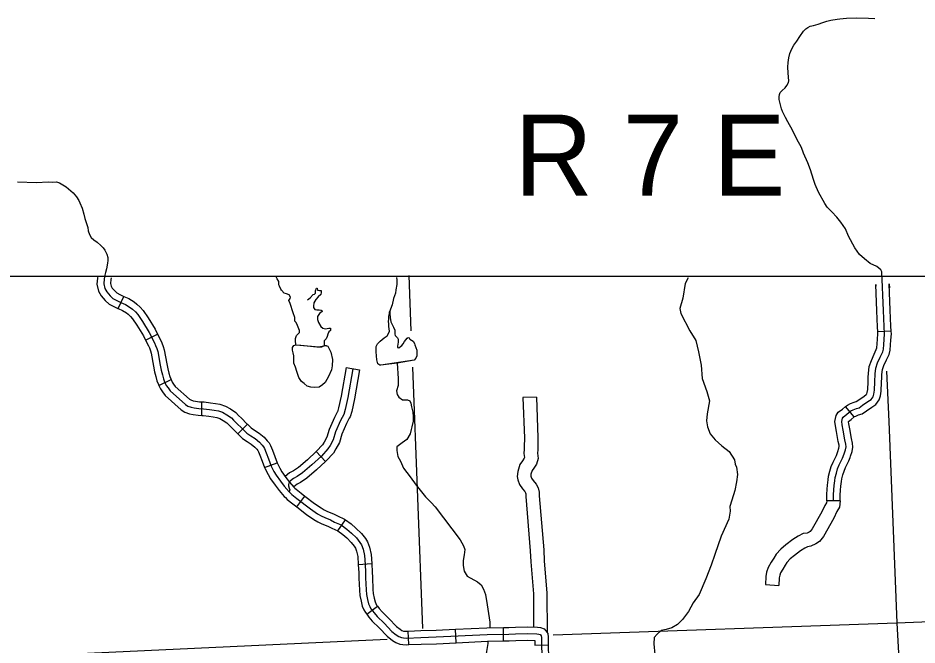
# Model space of a CAD drawing. Extents: x -5566 to 1759129, y -3726 to 731467.
# Drawn here: x -4614.7 to -4538.9, y 480.8 to 533.8 of the extents above; entities that cross this region are included whole.
import ezdxf

# ---------------------------------------------------------------- set-up
doc = ezdxf.new("R2010")
doc.units = 0
doc.layers.add('Default', color=7, linetype='Continuous')
doc.layers.add('R_No Plot', color=7, linetype='Continuous')

msp = doc.modelspace()

# ---------------------------------------------------------------- linework, layer by layer
at = {"layer": 'Default'}
for p, q in [((-4606.271, 509.255), (-4605.779, 510.282)), ((-4603.95, 506.571), (-4602.937, 507.092)), ((-4541.044, 507.331), (-4542.181, 507.275)), ((-4587.028, 504.264), (-4585.905, 504.072)), ((-4602.833, 502.765), (-4601.804, 503.252)), ((-4599.22, 500.231), (-4599.193, 501.37)), ((-4544.166, 500.106), (-4544.898, 500.978)), ((-4596.157, 498.672), (-4595.36, 499.486)), ((-4589.547, 497.175), (-4588.768, 496.344)), ((-4593.908, 495.823), (-4592.838, 496.213)), ((-4591.201, 492.503), (-4590.512, 493.41)), ((-4545.339, 493.025), (-4546.478, 493.025)), ((-4587.743, 490.482), (-4587.079, 491.408)), ((-4586.006, 487.651), (-4584.869, 487.728)), ((-4585.294, 483.437), (-4584.387, 484.126)), ((-4581.745, 480.873), (-4581.796, 482.011)), ((-4577.737, 481.033), (-4577.791, 482.171)), ((-4573.746, 481.186), (-4573.769, 482.325)), ((-4571.117, 480.842), (-4569.978, 480.866))]:
    msp.add_line(p, q, dxfattribs=at)
for points in [[(-4542.192, 504.659), (-4541.971, 505.159), (-4541.766, 505.585), (-4541.699, 505.828), (-4541.663, 506.225), (-4541.633, 506.629), (-4541.604, 507.129), (-4541.633, 507.731), (-4541.692, 509.083), (-4541.824, 512.355), (-4541.927, 512.531), (-4542.265, 512.811), (-4542.809, 513.046), (-4543.294, 513.443), (-4543.734, 513.825), (-4544.116, 514.383), (-4544.645, 515.368), (-4544.91, 515.971), (-4545.306, 516.559), (-4545.644, 516.955), (-4546.056, 517.411), (-4546.438, 517.823), (-4546.658, 518.131), (-4547.172, 519.065), (-4547.474, 519.719), (-4547.606, 520.137), (-4547.863, 520.975), (-4548.091, 521.548), (-4548.436, 522.374), (-4548.627, 522.845), (-4549.002, 523.55), (-4549.362, 524.3), (-4549.766, 525.005), (-4549.964, 525.373), (-4550.221, 525.887), (-4550.294, 526.115), (-4550.449, 526.666), (-4550.5, 526.901), (-4550.508, 527.122), (-4550.463, 527.328), (-4550.403, 527.481), (-4550.236, 527.666), (-4550.001, 527.893), (-4549.839, 528.077), (-4549.721, 528.349), (-4549.677, 528.467), (-4549.699, 528.783), (-4549.736, 529.15), (-4549.766, 529.642), (-4549.736, 530.017), (-4549.685, 530.414), (-4549.589, 530.782), (-4549.442, 531.171), (-4549.251, 531.487), (-4549.016, 531.818), (-4548.752, 532.229), (-4548.451, 532.685), (-4548.252, 532.883), (-4548.091, 532.986), (-4547.892, 533.082), (-4547.613, 533.148), (-4547.194, 533.273), (-4546.812, 533.412), (-4546.467, 533.523), (-4546.129, 533.589), (-4545.6, 533.692), (-4545.383, 533.721), (-4544.825, 533.765), (-4543.965, 533.787), (-4542.973, 533.773), (-4542.434, 533.745)], [(-4614.752, 519.942), (-4613.155, 519.893), (-4612.184, 519.942), (-4611.803, 519.936), (-4611.472, 519.946), (-4611.201, 519.874), (-4610.661, 519.518), (-4610.071, 519.026), (-4609.77, 518.688), (-4609.591, 518.381), (-4609.495, 518.175), (-4609.315, 517.717), (-4609.174, 517.213), (-4609.08, 516.852), (-4608.972, 516.506), (-4608.83, 516.088), (-4608.785, 515.825), (-4608.685, 515.516), (-4608.553, 515.24), (-4608.326, 515.043), (-4608.043, 514.853), (-4607.73, 514.589), (-4607.535, 514.384), (-4607.38, 514.177), (-4607.232, 513.857), (-4607.146, 513.55), (-4607.134, 513.31), (-4607.159, 513.083), (-4607.238, 512.604), (-4607.331, 512.297), (-4607.397, 512.078), (-4607.446, 511.761), (-4607.481, 511.341), (-4607.392, 510.933), (-4607.234, 510.651), (-4606.952, 510.337), (-4606.703, 510.11), (-4606.369, 509.943), (-4606.032, 509.772), (-4605.64, 509.584), (-4605.248, 509.351), (-4605.052, 509.201), (-4604.807, 508.971), (-4604.601, 508.746), (-4604.215, 508.163), (-4603.644, 507.221), (-4603.198, 506.354), (-4603.103, 506.146), (-4603.006, 505.876), (-4602.926, 505.632), (-4602.721, 504.481), (-4602.633, 504.044), (-4602.537, 503.644), (-4602.453, 503.32), (-4602.349, 503.073), (-4602.205, 502.768), (-4602.057, 502.546), (-4601.87, 502.296), (-4600.589, 501.157), (-4600.389, 501.023), (-4600.098, 500.923), (-4599.839, 500.865), (-4599.464, 500.807), (-4599.06, 500.797), (-4598.547, 500.74), (-4598.156, 500.673), (-4597.813, 500.616), (-4597.453, 500.499), (-4597.097, 500.29), (-4596.713, 500.03), (-4596.528, 499.832), (-4596.27, 499.581), (-4595.803, 499.123), (-4595.411, 498.739), (-4595.069, 498.514), (-4594.703, 498.272), (-4594.339, 497.975), (-4594.119, 497.731), (-4594.011, 497.59), (-4593.911, 497.422), (-4593.769, 497.08), (-4593.569, 496.555), (-4593.344, 495.938), (-4593.119, 495.506), (-4592.928, 495.172), (-4592.569, 494.664), (-4592.252, 494.247), (-4591.847, 493.785)], [(-4581.535, 507.382), (-4581.718, 512.048)], [(-4607.989, 511.976), (-4608.012, 511.829), (-4608.056, 511.303), (-4607.931, 510.729), (-4607.7, 510.317), (-4607.357, 509.935), (-4607.028, 509.635), (-4606.625, 509.434), (-4606.283, 509.261), (-4606.271, 509.255)], [(-4606.855, 511.857), (-4606.88, 511.694), (-4606.906, 511.378), (-4606.854, 511.138), (-4606.768, 510.985), (-4606.547, 510.739), (-4606.377, 510.584), (-4606.113, 510.452), (-4605.78, 510.283), (-4605.779, 510.282)], [(-4591.264, 506.195), (-4591.312, 506.545), (-4591.312, 506.729), (-4591.212, 506.979), (-4590.962, 507.229), (-4590.979, 507.396), (-4591.146, 507.813), (-4591.246, 508.063), (-4591.346, 508.196), (-4591.346, 508.496), (-4591.512, 508.88), (-4591.762, 509.68), (-4591.879, 509.93), (-4591.762, 510.097), (-4591.729, 510.214), (-4591.829, 510.397), (-4592.062, 510.497), (-4592.262, 510.564), (-4592.479, 510.797), (-4592.529, 510.881), (-4592.662, 511.131), (-4592.696, 511.248), (-4592.696, 511.431), (-4592.712, 511.548), (-4592.846, 511.765), (-4592.946, 511.931), (-4592.962, 511.979)], [(-4582.779, 511.88), (-4582.754, 511.683), (-4582.756, 511.27), (-4582.825, 510.824), (-4582.879, 510.539), (-4583.024, 510.104), (-4583.149, 509.571), (-4583.386, 508.982)], [(-4558.184, 511.838), (-4558.431, 511.381), (-4558.622, 510.118), (-4558.881, 509.243), (-4558.802, 508.826), (-4558.04, 507.384), (-4557.525, 506.559), (-4557.298, 505.611), (-4557.072, 504.458), (-4556.991, 503.336), (-4556.6, 502.238), (-4556.371, 501.449), (-4556.567, 500.35), (-4556.622, 499.783), (-4556.558, 499.267), (-4556.323, 498.68), (-4555.905, 498.156), (-4555.327, 497.657), (-4554.719, 497.172), (-4554.277, 496.489), (-4554.205, 496.111), (-4554.093, 495.857), (-4554.017, 495.25), (-4554.1, 494.62), (-4554.238, 493.895), (-4554.484, 493.077), (-4554.664, 492.537), (-4554.636, 492.136), (-4554.731, 491.473), (-4555.387, 490.02), (-4555.936, 488.484), (-4556.24, 487.584), (-4556.69, 486.424), (-4557.261, 485.105), (-4557.756, 484.404), (-4558.145, 483.682), (-4558.664, 482.984), (-4559.077, 482.582), (-4559.541, 482.299), (-4560.028, 482.16), (-4560.448, 482.062), (-4560.804, 481.761), (-4561.034, 481.483), (-4561.083, 480.938), (-4560.999, 480.034)], [(-4542.181, 507.275), (-4542.202, 507.705), (-4542.261, 509.059), (-4542.351, 511.286)], [(-4542.351, 511.286), (-4542.345, 511.139)], [(-4541.044, 507.331), (-4541.064, 507.757), (-4541.123, 509.107), (-4541.213, 511.332)], [(-4541.213, 511.332), (-4541.199, 510.992)], [(-4590.279, 509.996), (-4590.079, 510.146), (-4589.812, 510.429), (-4589.695, 510.463), (-4589.629, 510.563), (-4589.629, 510.746), (-4589.545, 510.98), (-4589.479, 510.963), (-4589.445, 510.813), (-4589.279, 510.763), (-4589.145, 510.763), (-4589.129, 510.713), (-4589.129, 510.613), (-4589.179, 510.429), (-4589.379, 510.246), (-4589.595, 510.013), (-4589.762, 509.729), (-4589.779, 509.462), (-4589.779, 509.329), (-4589.679, 509.162), (-4589.512, 509.145), (-4589.295, 509.145), (-4589.145, 509.129), (-4589.045, 509.062), (-4589.045, 508.995), (-4589.279, 508.845), (-4589.445, 508.579), (-4589.445, 508.328), (-4589.362, 508.078), (-4589.179, 507.745), (-4588.995, 507.595), (-4588.762, 507.545), (-4588.495, 507.595), (-4588.345, 507.595), (-4588.345, 507.411), (-4588.479, 507.278), (-4588.579, 507.094), (-4588.645, 506.894), (-4588.729, 506.694), (-4588.895, 506.527), (-4588.895, 506.144)], [(-4605.779, 510.282), (-4605.371, 510.087), (-4604.928, 509.823), (-4604.684, 509.636), (-4604.401, 509.372), (-4604.151, 509.097), (-4603.734, 508.468), (-4603.146, 507.499), (-4602.937, 507.092)], [(-4606.271, 509.255), (-4605.909, 509.082), (-4605.568, 508.879), (-4605.421, 508.765), (-4605.212, 508.571), (-4605.052, 508.395), (-4604.696, 507.858), (-4604.141, 506.943), (-4603.95, 506.571)], [(-4583.829, 506.777), (-4583.561, 506.952), (-4583.458, 507.148), (-4583.386, 507.333), (-4583.397, 507.55), (-4583.417, 507.725), (-4583.438, 507.972), (-4583.448, 508.158), (-4583.438, 508.353), (-4583.417, 508.601), (-4583.386, 508.817), (-4583.386, 508.982), (-4583.335, 508.992), (-4583.335, 508.817), (-4583.304, 508.487), (-4583.263, 508.137), (-4583.047, 507.684), (-4582.933, 507.416), (-4582.913, 507.272), (-4582.913, 507.138), (-4582.913, 507.076), (-4582.902, 506.973), (-4582.707, 506.787), (-4582.655, 506.653), (-4582.655, 506.416), (-4582.686, 506.066), (-4582.686, 505.973), (-4582.583, 505.922), (-4582.459, 506.035), (-4582.336, 506.128), (-4582.223, 506.262), (-4582.109, 506.458), (-4581.883, 506.746), (-4581.79, 506.798), (-4581.728, 506.787), (-4581.656, 506.674), (-4581.378, 506.499), (-4581.254, 506.313), (-4581.234, 506.179)], [(-4602.937, 507.092), (-4602.685, 506.602), (-4602.575, 506.36), (-4602.467, 506.061), (-4602.372, 505.772), (-4602.161, 504.586), (-4602.077, 504.166), (-4601.985, 503.783), (-4601.912, 503.503), (-4601.829, 503.306), (-4601.804, 503.252)], [(-4581.234, 506.179), (-4581.069, 505.747), (-4581.069, 505.273), (-4581.151, 505.067), (-4581.296, 504.902), (-4582.717, 504.644), (-4584.118, 504.459), (-4584.2, 504.479), (-4584.355, 504.582), (-4584.447, 504.922), (-4584.509, 505.592), (-4584.509, 505.809), (-4584.488, 506.045), (-4584.385, 506.272), (-4584.149, 506.489), (-4583.829, 506.777)], [(-4542.977, 503.454), (-4542.964, 503.766), (-4542.915, 504.355), (-4542.719, 504.875), (-4542.489, 505.398), (-4542.301, 505.786), (-4542.262, 505.93), (-4542.23, 506.272), (-4542.202, 506.666), (-4542.174, 507.131), (-4542.181, 507.275)], [(-4541.839, 503.408), (-4541.827, 503.695), (-4541.793, 504.102), (-4541.664, 504.444), (-4541.454, 504.92), (-4541.23, 505.385), (-4541.137, 505.726), (-4541.095, 506.178), (-4541.065, 506.591), (-4541.034, 507.126), (-4541.044, 507.331)], [(-4603.95, 506.571), (-4603.711, 506.105), (-4603.631, 505.931), (-4603.545, 505.69), (-4603.48, 505.493), (-4603.281, 504.375), (-4603.19, 503.921), (-4603.09, 503.506), (-4602.994, 503.137), (-4602.87, 502.841), (-4602.833, 502.765)], [(-4591.297, 504.294), (-4591.447, 504.628), (-4591.447, 504.878), (-4591.447, 505.262), (-4591.514, 505.512), (-4591.564, 505.728), (-4591.547, 505.962), (-4591.431, 506.129), (-4591.264, 506.195), (-4590.847, 506.162), (-4589.497, 506.012), (-4589.297, 506.012), (-4589.08, 506.029), (-4588.83, 506.129), (-4588.714, 506.129), (-4588.58, 506.079), (-4588.33, 505.578), (-4588.18, 504.945)], [(-4591.264, 506.195), (-4589.297, 506.012), (-4588.83, 506.129), (-4588.58, 506.079)], [(-4588.18, 504.945), (-4588.197, 504.411), (-4588.264, 504.078), (-4588.514, 503.527), (-4588.797, 503.01), (-4589.014, 502.81), (-4589.314, 502.627), (-4589.68, 502.594), (-4589.997, 502.61), (-4590.33, 502.71), (-4590.58, 502.91), (-4590.797, 503.094), (-4591.014, 503.444), (-4591.181, 503.928), (-4591.297, 504.294)], [(-4581.296, 504.902), (-4584.118, 504.459)], [(-4582.717, 504.644), (-4582.652, 503.338), (-4582.655, 502.748), (-4582.779, 502.316), (-4582.727, 501.986), (-4582.583, 501.782), (-4582.284, 501.535), (-4581.862, 501.543), (-4581.646, 501.473), (-4581.563, 501.257), (-4581.522, 500.948), (-4581.409, 500.494), (-4581.368, 500.134), (-4581.387, 499.732), (-4581.493, 499.273), (-4581.533, 499.031), (-4581.618, 498.687), (-4581.917, 498.198), (-4582.298, 497.912), (-4582.748, 497.59), (-4582.768, 497.27), (-4582.665, 496.765), (-4582.455, 496.362), (-4582.183, 495.788), (-4581.637, 495.037), (-4581.131, 494.345), (-4580.337, 493.362), (-4579.857, 492.882), (-4579.52, 492.51), (-4577.423, 489.719), (-4577.13, 489.227), (-4577.015, 488.904), (-4577.06, 488.459), (-4577.159, 487.978), (-4577.146, 487.559), (-4577.083, 487.081), (-4576.815, 486.669), (-4575.949, 486.182)], [(-4545.909, 493.025), (-4545.909, 493.523), (-4545.881, 493.952), (-4545.853, 494.298), (-4545.812, 494.713), (-4545.77, 494.99), (-4545.673, 495.364), (-4545.563, 495.723), (-4545.425, 496.055), (-4545.148, 496.633), (-4545.01, 496.992), (-4544.899, 497.324), (-4544.857, 497.574), (-4544.871, 497.795), (-4544.954, 498.155), (-4545.106, 498.985), (-4545.189, 499.441), (-4545.217, 499.704), (-4545.189, 499.87), (-4545.162, 499.995), (-4545.093, 500.092), (-4544.788, 500.327), (-4544.443, 500.617), (-4544.249, 500.7), (-4543.986, 500.811), (-4543.751, 500.88), (-4543.461, 501.088), (-4543.004, 501.392), (-4542.741, 501.572), (-4542.575, 501.807), (-4542.506, 502.029), (-4542.451, 502.347), (-4542.423, 503.053), (-4542.396, 503.731), (-4542.354, 504.229), (-4542.192, 504.659)], [(-4586.467, 504.168), (-4586.883, 501.733), (-4587.117, 500.716), (-4587.233, 500.316), (-4587.5, 499.799), (-4587.934, 498.832), (-4588.134, 498.165), (-4588.384, 497.698), (-4588.567, 497.398), (-4589.117, 496.797), (-4589.917, 496.047), (-4590.701, 495.38), (-4591.176, 495.063), (-4591.484, 494.896), (-4591.734, 494.7), (-4591.817, 494.617), (-4591.872, 494.521), (-4591.901, 494.405), (-4591.888, 494.284), (-4591.842, 494.1), (-4591.792, 493.958), (-4591.797, 493.875), (-4591.847, 493.785)], [(-4587.028, 504.264), (-4587.442, 501.845), (-4587.668, 500.859), (-4587.765, 500.528), (-4587.776, 500.506)], [(-4585.905, 504.072), (-4586.325, 501.621), (-4586.565, 500.572), (-4586.702, 500.104), (-4586.764, 499.984)], [(-4580.553, 482.224), (-4581.415, 504.309)], [(-4541.441, 503.971), (-4541.244, 499.717), (-4540.573, 482.722)], [(-4601.804, 503.252), (-4601.708, 503.049), (-4601.592, 502.875), (-4601.448, 502.684), (-4600.24, 501.609), (-4600.135, 501.538), (-4599.942, 501.472), (-4599.733, 501.425), (-4599.413, 501.375), (-4599.193, 501.37)], [(-4544.898, 500.978), (-4544.744, 501.108), (-4544.472, 501.225), (-4544.178, 501.348), (-4544.004, 501.4), (-4543.784, 501.557), (-4543.323, 501.864), (-4543.148, 501.984), (-4543.092, 502.063), (-4543.061, 502.163), (-4543.019, 502.407), (-4542.992, 503.075), (-4542.977, 503.454)], [(-4544.166, 500.106), (-4544.141, 500.127), (-4544.026, 500.176), (-4543.795, 500.274), (-4543.498, 500.361), (-4543.137, 500.619), (-4542.685, 500.92), (-4542.335, 501.16), (-4542.058, 501.552), (-4541.951, 501.894), (-4541.883, 502.287), (-4541.854, 503.03), (-4541.839, 503.408)], [(-4602.833, 502.765), (-4602.702, 502.487), (-4602.522, 502.217), (-4602.291, 501.909), (-4600.938, 500.705), (-4600.644, 500.509), (-4600.253, 500.375), (-4599.946, 500.305), (-4599.515, 500.238), (-4599.22, 500.231)], [(-4599.193, 501.37), (-4599.022, 501.366), (-4598.468, 501.304), (-4598.061, 501.235), (-4597.677, 501.171), (-4597.218, 501.021), (-4596.793, 500.772), (-4596.34, 500.466), (-4596.121, 500.23), (-4595.872, 499.989), (-4595.404, 499.529), (-4595.36, 499.486)], [(-4570.977, 501.773), (-4572.116, 501.733), (-4571.996, 498.307), (-4571.998, 497.603), (-4572.001, 497.389), (-4572.043, 497.012), (-4571.993, 496.689), (-4572.018, 496.616), (-4572.151, 496.404), (-4572.381, 496.073), (-4572.555, 495.498), (-4572.607, 495.072), (-4572.538, 494.787), (-4572.403, 494.392), (-4572.148, 494.043), (-4571.959, 493.808), (-4571.9, 493.696), (-4571.875, 493.603), (-4571.875, 493.388), (-4571.493, 488.806), (-4571.462, 487.869), (-4571.226, 485.157), (-4571.212, 482.37)], [(-4570.977, 501.773), (-4570.857, 498.326), (-4570.859, 497.595), (-4570.863, 497.319), (-4570.894, 497.037), (-4570.824, 496.584), (-4570.984, 496.12), (-4571.201, 495.776), (-4571.342, 495.572), (-4571.436, 495.261), (-4571.451, 495.138), (-4571.444, 495.106), (-4571.381, 494.924), (-4571.245, 494.737), (-4571.002, 494.436), (-4570.834, 494.115), (-4570.736, 493.755), (-4570.736, 493.435), (-4570.355, 488.872), (-4570.325, 487.938), (-4570.087, 485.21), (-4570.071, 481.91)], [(-4545.581, 497.094), (-4545.546, 497.185), (-4545.453, 497.462), (-4545.43, 497.603), (-4545.437, 497.713), (-4545.512, 498.039), (-4545.667, 498.883), (-4545.754, 499.361), (-4545.792, 499.722), (-4545.749, 499.979), (-4545.693, 500.231), (-4545.507, 500.491), (-4545.146, 500.77), (-4544.898, 500.978)], [(-4599.22, 500.231), (-4599.098, 500.228), (-4598.627, 500.176), (-4598.251, 500.112), (-4597.949, 500.061), (-4597.688, 499.976), (-4597.401, 499.808), (-4597.085, 499.595), (-4596.935, 499.433), (-4596.667, 499.174), (-4596.202, 498.716), (-4596.157, 498.672)], [(-4587.776, 500.506), (-4588.014, 500.046), (-4588.468, 499.031), (-4588.663, 498.383), (-4588.878, 497.981), (-4589.024, 497.742), (-4589.522, 497.198), (-4589.547, 497.175)], [(-4586.764, 499.984), (-4586.987, 499.552), (-4587.399, 498.633), (-4587.604, 497.946), (-4587.889, 497.415), (-4588.11, 497.054), (-4588.712, 496.397), (-4588.768, 496.344)], [(-4544.517, 496.686), (-4544.473, 496.8), (-4544.344, 497.187), (-4544.285, 497.544), (-4544.306, 497.877), (-4544.396, 498.27), (-4544.546, 499.087), (-4544.625, 499.522), (-4544.643, 499.687), (-4544.636, 499.724), (-4544.431, 499.883), (-4544.166, 500.106)], [(-4595.36, 499.486), (-4595.052, 499.185), (-4594.756, 498.99), (-4594.365, 498.732), (-4593.944, 498.388), (-4593.681, 498.095), (-4593.539, 497.911), (-4593.401, 497.678), (-4593.24, 497.291), (-4593.036, 496.754), (-4592.838, 496.213)], [(-4596.157, 498.672), (-4595.77, 498.294), (-4595.383, 498.039), (-4595.041, 497.813), (-4594.733, 497.561), (-4594.557, 497.366), (-4594.483, 497.269), (-4594.421, 497.166), (-4594.299, 496.87), (-4594.103, 496.356), (-4593.908, 495.823)], [(-4589.547, 497.175), (-4590.297, 496.472), (-4591.044, 495.835), (-4591.47, 495.552), (-4591.797, 495.374), (-4592.168, 495.084)], [(-4546.478, 493.025), (-4546.478, 493.542), (-4546.449, 493.993), (-4546.421, 494.349), (-4546.377, 494.784), (-4546.329, 495.104), (-4546.222, 495.519), (-4546.099, 495.917), (-4545.945, 496.288), (-4545.671, 496.858), (-4545.581, 497.094)], [(-4592.838, 496.213), (-4592.822, 496.168), (-4592.619, 495.779), (-4592.447, 495.479), (-4592.109, 495), (-4591.811, 494.607), (-4591.431, 494.175), (-4591.348, 494.092), (-4591.245, 493.989), (-4590.838, 493.658), (-4590.512, 493.41)], [(-4588.768, 496.344), (-4589.537, 495.622), (-4590.357, 494.925), (-4590.882, 494.575), (-4591.171, 494.418), (-4591.452, 494.198)], [(-4545.339, 493.025), (-4545.339, 493.505), (-4545.313, 493.911), (-4545.286, 494.247), (-4545.246, 494.643), (-4545.211, 494.876), (-4545.125, 495.208), (-4545.027, 495.53), (-4544.904, 495.823), (-4544.624, 496.407), (-4544.517, 496.686)], [(-4593.908, 495.823), (-4593.867, 495.708), (-4593.619, 495.232), (-4593.408, 494.866), (-4593.029, 494.327), (-4592.694, 493.886), (-4592.263, 493.395), (-4592.154, 493.287), (-4592.009, 493.142), (-4591.542, 492.762), (-4591.201, 492.503)], [(-4591.847, 493.785), (-4591.751, 493.689), (-4591.627, 493.565), (-4591.19, 493.21), (-4590.042, 492.338), (-4589.455, 491.931), (-4589.149, 491.754), (-4588.839, 491.604), (-4588.35, 491.399), (-4588.002, 491.222), (-4587.46, 490.981), (-4586.96, 490.622), (-4586.593, 490.297), (-4586.168, 489.88)], [(-4590.512, 493.41), (-4589.707, 492.799), (-4589.15, 492.413), (-4588.881, 492.257), (-4588.605, 492.123), (-4588.111, 491.917), (-4587.757, 491.737), (-4587.175, 491.477), (-4587.079, 491.408)], [(-4546.478, 493.025), (-4546.512, 492.854), (-4546.636, 492.625), (-4546.897, 492.089), (-4547.711, 490.649), (-4547.893, 490.418), (-4547.961, 490.371), (-4548.143, 490.288), (-4548.463, 490.245), (-4548.884, 490.025), (-4549.343, 489.75), (-4549.934, 489.291), (-4550.357, 488.928), (-4550.744, 488.509), (-4550.953, 488.187), (-4551.165, 487.848), (-4551.438, 487.399), (-4551.569, 486.987), (-4551.621, 486.641), (-4551.664, 485.952), (-4550.527, 485.881)], [(-4545.339, 493.025), (-4545.416, 492.483), (-4545.624, 492.103), (-4545.888, 491.56), (-4546.762, 490.012), (-4547.105, 489.578), (-4547.397, 489.376), (-4547.824, 489.182), (-4548.112, 489.143), (-4548.327, 489.031), (-4548.698, 488.808), (-4549.214, 488.408), (-4549.565, 488.107), (-4549.842, 487.807), (-4549.992, 487.575), (-4550.195, 487.251), (-4550.393, 486.924), (-4550.456, 486.728), (-4550.487, 486.521), (-4550.527, 485.881)], [(-4591.201, 492.503), (-4590.377, 491.877), (-4589.761, 491.45), (-4589.416, 491.25), (-4589.073, 491.084), (-4588.589, 490.882), (-4588.247, 490.708), (-4587.745, 490.484), (-4587.743, 490.482)], [(-4587.079, 491.408), (-4586.604, 491.068), (-4586.205, 490.714), (-4585.742, 490.26), (-4585.408, 489.83), (-4585.232, 489.544), (-4585.055, 489.096), (-4584.919, 488.476), (-4584.869, 487.728)], [(-4587.743, 490.482), (-4587.316, 490.176), (-4586.982, 489.88), (-4586.594, 489.5), (-4586.345, 489.18), (-4586.255, 489.032), (-4586.148, 488.763), (-4586.05, 488.316), (-4586.006, 487.651)], [(-4586.168, 489.88), (-4585.877, 489.505), (-4585.743, 489.288), (-4585.602, 488.93), (-4585.485, 488.396), (-4585.435, 487.654), (-4585.402, 486.995), (-4585.39, 486.515), (-4585.343, 485.503), (-4585.312, 485.12), (-4585.217, 484.674), (-4585.137, 484.31), (-4585.035, 484.082), (-4584.934, 483.905), (-4584.678, 483.567), (-4584.408, 483.257), (-4583.828, 482.683), (-4583.172, 481.998), (-4582.805, 481.7), (-4582.577, 481.569), (-4582.356, 481.473), (-4582.184, 481.447), (-4581.928, 481.435), (-4580.718, 481.489), (-4579.426, 481.523), (-4575.134, 481.729), (-4573.293, 481.765), (-4572.737, 481.791), (-4571.702, 481.817), (-4570.934, 481.791), (-4570.765, 481.765), (-4570.666, 481.732), (-4570.641, 481.703), (-4570.574, 481.605), (-4570.559, 481.471), (-4570.553, 481.131), (-4570.522, 479.704)], [(-4584.869, 487.728), (-4584.866, 487.688), (-4584.832, 487.016), (-4584.821, 486.535), (-4584.775, 485.539), (-4584.747, 485.203), (-4584.661, 484.795), (-4584.593, 484.49), (-4584.526, 484.34), (-4584.458, 484.219), (-4584.387, 484.126)], [(-4586.006, 487.651), (-4586.003, 487.62), (-4585.971, 486.974), (-4585.96, 486.495), (-4585.912, 485.466), (-4585.877, 485.037), (-4585.774, 484.554), (-4585.68, 484.13), (-4585.544, 483.825), (-4585.41, 483.59), (-4585.294, 483.437)], [(-4575.949, 486.182), (-4575.631, 485.938), (-4575.435, 485.546), (-4575.279, 485.122), (-4575.121, 484.244), (-4575.009, 483.498), (-4574.912, 482.765), (-4574.92, 482.303)], [(-4584.387, 484.126), (-4584.235, 483.927), (-4583.992, 483.647), (-4583.422, 483.083), (-4582.785, 482.417), (-4582.482, 482.171), (-4582.321, 482.079), (-4582.198, 482.025), (-4582.13, 482.015), (-4581.927, 482.005), (-4581.796, 482.011)], [(-4585.294, 483.437), (-4585.12, 483.208), (-4584.823, 482.867), (-4584.234, 482.284), (-4583.558, 481.578), (-4583.129, 481.229), (-4582.834, 481.06), (-4582.514, 480.92), (-4582.239, 480.88), (-4581.928, 480.865), (-4581.745, 480.873)], [(-4569.576, 481.715), (-4540.573, 482.722)], [(-4540.573, 482.722), (-4531.444, 483.08)], [(-4540.573, 482.722), (-4539.484, 462.843), (-4539.197, 453.481)], [(-4581.796, 482.011), (-4580.738, 482.058), (-4579.447, 482.092), (-4577.791, 482.171)], [(-4577.791, 482.171), (-4575.153, 482.298), (-4573.769, 482.325)], [(-4573.769, 482.325), (-4573.312, 482.334), (-4572.757, 482.36), (-4571.699, 482.386), (-4570.882, 482.359), (-4570.632, 482.321), (-4570.334, 482.223), (-4570.187, 482.048), (-4570.024, 481.811), (-4569.989, 481.508), (-4569.984, 481.142), (-4569.978, 480.866)], [(-4620.321, 479.614), (-4583.569, 481.334)], [(-4581.745, 480.873), (-4580.698, 480.92), (-4579.405, 480.953), (-4577.737, 481.033)], [(-4577.737, 481.033), (-4575.115, 481.159), (-4573.746, 481.186)], [(-4575.064, 481.162), (-4575.064, 480.957), (-4575.188, 480.307), (-4575.341, 479.393), (-4575.493, 478.591), (-4575.493, 477.968), (-4575.341, 477.47), (-4574.926, 476.46), (-4574.525, 475.63), (-4573.978, 475.027), (-4573.639, 474.326), (-4573.439, 473.68), (-4573.371, 472.782), (-4573.392, 471.675)], [(-4573.746, 481.186), (-4573.274, 481.196), (-4572.717, 481.222), (-4571.704, 481.247), (-4571.124, 481.227), (-4571.123, 481.121), (-4571.117, 480.842)], [(-4569.978, 480.866), (-4569.953, 479.726), (-4569.803, 476.878)]]:
    msp.add_lwpolyline(points, dxfattribs=at)
at = {"layer": 'R_No Plot'}
msp.add_lwpolyline([(-5018.988, 168.239), (-5018.988, 511.979), (-4446.603, 511.979), (-4446.603, 160.504), (-4913.433, 160.504)], dxfattribs=at)

# ---------------------------------------------------------------- texts
at = {"layer": 'Default'}
msp.add_text('R 7 E', height=6.8348, dxfattribs=at).set_placement((-4572.825, 518.792))

doc.saveas('drawing.dxf')
